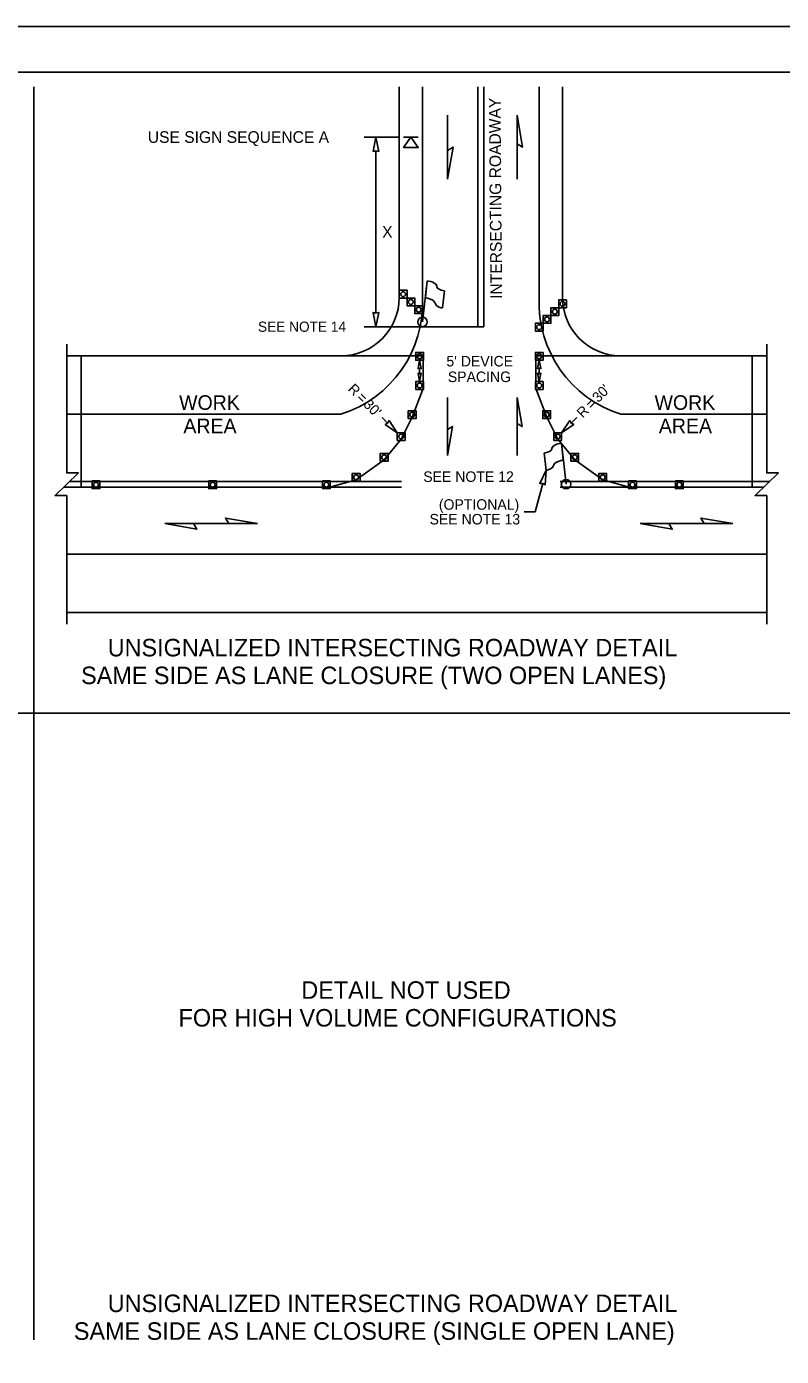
# Model space of a CAD drawing. Extents: x 99999.1 to 100095.7, y 99995 to 100010.7.
# Drawn here: x 100065.2 to 100070.38, y 100001.57 to 100010.69 of the extents above; entities that cross this region are included whole.
import ezdxf

# ---------------------------------------------------------------- set-up
doc = ezdxf.new("R2010")
doc.units = 0
for name, color, linetype in [('RD_ED_ShoulderPavedEdge', 7, 'Continuous'), ('RD_MK_LineDblYellowCenter', 7, 'Continuous'), ('RD_MK_LineEdgeWhite', 7, 'Continuous'), ('RD_MK_LineStop', 7, 'Continuous'), ('SH_DE_DetailBody1Text', 7, 'Continuous'), ('SH_DE_DetailHeading2Text', 7, 'Continuous'), ('SH_GI_PlotLimits', 7, 'Continuous'), ('SH_GI_SheetBorder', 7, 'Continuous'), ('TR_WZ_FlaggingStation', 7, 'Continuous'), ('TR_WZ_PortableSignMountBlk-Org', 7, 'Continuous'), ('TR_WZ_TrafficCone', 7, 'Continuous'), ('TR_WZ_WorkAreaLabel', 7, 'Continuous'), ('TR_WZ_WorkZoneDetails', 7, 'Continuous'), ('TR_WZ_WorkZoneTextCurrent', 7, 'Continuous')]:
    doc.layers.add(name, color=color, linetype=linetype)

msp = doc.modelspace()

# ---------------------------------------------------------------- linework, layer by layer
at = {"layer": 'RD_ED_ShoulderPavedEdge'}
for p, q in [((100065.475, 100008.4304), (100067.355, 100008.4304)), ((100069.275, 100008.4304), (100070.275, 100008.4304)), ((100065.475, 100006.6704), (100070.275, 100006.6704))]:
    msp.add_line(p, q, dxfattribs=at)
for points in [[(100067.755, 100010.275), (100067.755, 100008.8304)], [(100068.875, 100010.275), (100068.875, 100008.8304)]]:
    msp.add_lwpolyline(points, dxfattribs=at)
for centre, start, end in [((100067.355, 100008.8304), 270, 0), ((100069.275, 100008.8304), 180, 270)]:
    msp.add_arc(centre, 0.4, start, end, dxfattribs=at)
at = {"layer": 'RD_MK_LineDblYellowCenter'}
for p, q in [((100068.295, 100010.275), (100068.295, 100008.6304)), ((100068.335, 100010.275), (100068.335, 100008.6304)), ((100065.4543, 100007.5305), (100067.7712, 100007.5305)), ((100065.4957, 100007.5704), (100067.7712, 100007.5704)), ((100068.8588, 100007.5704), (100070.2957, 100007.5704)), ((100068.8588, 100007.5305), (100070.2543, 100007.5305))]:
    msp.add_line(p, q, dxfattribs=at)
at = {"layer": 'RD_MK_LineEdgeWhite'}
for p, q in [((100067.915, 100008.8304), (100067.915, 100010.275)), ((100068.715, 100008.8304), (100068.715, 100010.275)), ((100065.475, 100008.0305), (100067.355, 100008.0305)), ((100069.275, 100008.0305), (100070.275, 100008.0305)), ((100065.475, 100007.0704), (100070.275, 100007.0704))]:
    msp.add_line(p, q, dxfattribs=at)
for centre, start, end in [((100067.1158, 100008.7939), 287.39477, 2.62119), ((100069.5142, 100008.7939), 177.37881, 252.60523)]:
    msp.add_arc(centre, 0.8, start, end, dxfattribs=at)
at = {"layer": 'RD_MK_LineStop'}
msp.add_line((100067.899, 100008.6304), (100068.335, 100008.6304), dxfattribs=at)
at = {"layer": 'SH_GI_PlotLimits'}
msp.add_lwpolyline([(100059.0625, 99999.6875), (100076.0625, 99999.6875), (100076.0625, 100010.6875), (100059.0625, 100010.6875)], close=True, dxfattribs=at)
at = {"layer": 'SH_GI_SheetBorder'}
msp.add_line((100060, 100010.375), (100075.75, 100010.375), dxfattribs=at)
at = {"layer": 'TR_WZ_FlaggingStation'}
for p, q in [((100067.915, 100008.6629), (100067.9471, 100008.9439)), ((100067.934, 100008.8299), (100067.9471, 100008.9442)), ((100068.065, 100008.8764), (100068.0517, 100008.7592)), ((100067.934, 100008.8299), (100067.934, 100008.8299)), ((100068.7487, 100007.7639), (100068.762, 100007.6467)), ((100068.8797, 100007.7174), (100068.8667, 100007.8317)), ((100068.8988, 100007.5504), (100068.8667, 100007.8314)), ((100068.8797, 100007.7174), (100068.8797, 100007.7174))]:
    msp.add_line(p, q, dxfattribs=at)
for points in [[(100067.9471, 100008.9442), (100067.9528, 100008.9429), (100067.9707, 100008.9395), (100067.9845, 100008.9353), (100067.9942, 100008.9292), (100068.0027, 100008.9245), (100068.0084, 100008.9177), (100068.0126, 100008.9098), (100068.0131, 100008.9037), (100068.0185, 100008.8944), (100068.0293, 100008.887), (100068.0417, 100008.8818), (100068.065, 100008.8764)], [(100068.0517, 100008.7592), (100068.0436, 100008.7606), (100068.0259, 100008.7653), (100068.0103, 100008.7758), (100068.0037, 100008.7863), (100067.9998, 100008.7966), (100067.9907, 100008.8075), (100067.9798, 100008.8137), (100067.9624, 100008.8208), (100067.934, 100008.8299)], [(100068.8667, 100007.8317), (100068.8609, 100007.8304), (100068.8431, 100007.827), (100068.8293, 100007.8228), (100068.8196, 100007.8167), (100068.8111, 100007.812), (100068.8054, 100007.8052), (100068.8012, 100007.7973), (100068.8006, 100007.7912), (100068.7953, 100007.7819), (100068.7845, 100007.7745), (100068.7721, 100007.7693), (100068.7487, 100007.7639)], [(100068.762, 100007.6467), (100068.7702, 100007.6481), (100068.7879, 100007.6528), (100068.8035, 100007.6633), (100068.81, 100007.6738), (100068.814, 100007.6841), (100068.823, 100007.695), (100068.834, 100007.7012), (100068.8514, 100007.7083), (100068.8797, 100007.7174)]]:
    msp.add_lwpolyline(points, dxfattribs=at)
for centre in [(100067.915, 100008.6629), (100068.8988, 100007.5504)]:
    msp.add_circle(centre, 0.0325, dxfattribs=at)
at = {"layer": 'TR_WZ_PortableSignMountBlk-Org'}
msp.add_line((100067.785, 100009.9304), (100067.885, 100009.9304), dxfattribs=at)
msp.add_lwpolyline([(100067.8349, 100009.9304), (100067.885, 100009.8586), (100067.785, 100009.8586)], close=True, dxfattribs=at)
at = {"layer": 'TR_WZ_TrafficCone'}
for points in [[(100067.8083, 100008.8803), (100067.8083, 100008.827), (100067.755, 100008.827), (100067.755, 100008.8803), (100067.8083, 100008.8803)], [(100067.755, 100008.8803), (100067.755, 100008.827), (100067.8083, 100008.827), (100067.8083, 100008.8803), (100067.755, 100008.8803)], [(100067.8617, 100008.827), (100067.8617, 100008.7736), (100067.8083, 100008.7736), (100067.8083, 100008.827), (100067.8617, 100008.827)], [(100067.8083, 100008.827), (100067.8083, 100008.7736), (100067.8617, 100008.7736), (100067.8617, 100008.827), (100067.8083, 100008.827)], [(100067.915, 100008.7736), (100067.915, 100008.7203), (100067.8617, 100008.7203), (100067.8617, 100008.7736), (100067.915, 100008.7736)], [(100067.8617, 100008.7736), (100067.8617, 100008.7203), (100067.915, 100008.7203), (100067.915, 100008.7736), (100067.8617, 100008.7736)], [(100068.8483, 100008.7605), (100068.795, 100008.7605), (100068.795, 100008.7071), (100068.8483, 100008.7071), (100068.8483, 100008.7605)], [(100068.8483, 100008.7071), (100068.795, 100008.7071), (100068.795, 100008.7605), (100068.8483, 100008.7605), (100068.8483, 100008.7071)], [(100068.9016, 100008.8138), (100068.8483, 100008.8138), (100068.8483, 100008.7605), (100068.9016, 100008.7605), (100068.9016, 100008.8138)], [(100068.9016, 100008.7605), (100068.8483, 100008.7605), (100068.8483, 100008.8138), (100068.9016, 100008.8138), (100068.9016, 100008.7605)], [(100068.795, 100008.7071), (100068.7416, 100008.7071), (100068.7416, 100008.6538), (100068.795, 100008.6538), (100068.795, 100008.7071)], [(100068.795, 100008.6538), (100068.7416, 100008.6538), (100068.7416, 100008.7071), (100068.795, 100008.7071), (100068.795, 100008.6538)], [(100068.7416, 100008.6538), (100068.6883, 100008.6538), (100068.6883, 100008.6005), (100068.7416, 100008.6005), (100068.7416, 100008.6538)], [(100068.7416, 100008.6005), (100068.6883, 100008.6005), (100068.6883, 100008.6538), (100068.7416, 100008.6538), (100068.7416, 100008.6005)], [(100067.8684, 100008.4538), (100067.9217, 100008.4538), (100067.9217, 100008.4005), (100067.8684, 100008.4005), (100067.8684, 100008.4538)], [(100067.8684, 100008.4005), (100067.9217, 100008.4005), (100067.9217, 100008.4538), (100067.8684, 100008.4538), (100067.8684, 100008.4005)], [(100068.7416, 100008.4538), (100068.6883, 100008.4538), (100068.6883, 100008.4005), (100068.7416, 100008.4005), (100068.7416, 100008.4538)], [(100068.7416, 100008.4005), (100068.6883, 100008.4005), (100068.6883, 100008.4538), (100068.7416, 100008.4538), (100068.7416, 100008.4005)], [(100067.8684, 100008.2538), (100067.9217, 100008.2538), (100067.9217, 100008.2005), (100067.8684, 100008.2005), (100067.8684, 100008.2538)], [(100067.8684, 100008.2005), (100067.9217, 100008.2005), (100067.9217, 100008.2538), (100067.8684, 100008.2538), (100067.8684, 100008.2005)], [(100068.7416, 100008.2538), (100068.6883, 100008.2538), (100068.6883, 100008.2005), (100068.7416, 100008.2005), (100068.7416, 100008.2538)], [(100068.7416, 100008.2005), (100068.6883, 100008.2005), (100068.6883, 100008.2538), (100068.7416, 100008.2538), (100068.7416, 100008.2005)], [(100067.8173, 100008.0538), (100067.8707, 100008.0538), (100067.8707, 100008.0005), (100067.8173, 100008.0005), (100067.8173, 100008.0538)], [(100067.8173, 100008.0005), (100067.8707, 100008.0005), (100067.8707, 100008.0538), (100067.8173, 100008.0538), (100067.8173, 100008.0005)], [(100068.7927, 100008.0538), (100068.7393, 100008.0538), (100068.7393, 100008.0005), (100068.7927, 100008.0005), (100068.7927, 100008.0538)], [(100068.7927, 100008.0005), (100068.7393, 100008.0005), (100068.7393, 100008.0538), (100068.7927, 100008.0538), (100068.7927, 100008.0005)], [(100067.7417, 100007.9038), (100067.795, 100007.9038), (100067.795, 100007.8505), (100067.7417, 100007.8505), (100067.7417, 100007.9038)], [(100067.7417, 100007.8505), (100067.795, 100007.8505), (100067.795, 100007.9038), (100067.7417, 100007.9038), (100067.7417, 100007.8505)], [(100068.8683, 100007.9038), (100068.815, 100007.9038), (100068.815, 100007.8505), (100068.8683, 100007.8505), (100068.8683, 100007.9038)], [(100068.8683, 100007.8505), (100068.815, 100007.8505), (100068.815, 100007.9038), (100068.8683, 100007.9038), (100068.8683, 100007.8505)], [(100067.6247, 100007.7615), (100067.6781, 100007.7615), (100067.6781, 100007.7082), (100067.6247, 100007.7082), (100067.6247, 100007.7615)], [(100067.6247, 100007.7082), (100067.6781, 100007.7082), (100067.6781, 100007.7615), (100067.6247, 100007.7615), (100067.6247, 100007.7082)], [(100068.9853, 100007.7615), (100068.9319, 100007.7615), (100068.9319, 100007.7082), (100068.9853, 100007.7082), (100068.9853, 100007.7615)], [(100068.9853, 100007.7082), (100068.9319, 100007.7082), (100068.9319, 100007.7615), (100068.9853, 100007.7615), (100068.9853, 100007.7082)], [(100065.649, 100007.5738), (100065.7024, 100007.5738), (100065.7024, 100007.5205), (100065.649, 100007.5205), (100065.649, 100007.5738)], [(100065.649, 100007.5205), (100065.7024, 100007.5205), (100065.7024, 100007.5738), (100065.649, 100007.5738), (100065.649, 100007.5205)], [(100066.449, 100007.5738), (100066.5024, 100007.5738), (100066.5024, 100007.5205), (100066.449, 100007.5205), (100066.449, 100007.5738)], [(100066.449, 100007.5205), (100066.5024, 100007.5205), (100066.5024, 100007.5738), (100066.449, 100007.5738), (100066.449, 100007.5205)], [(100067.229, 100007.5738), (100067.2824, 100007.5738), (100067.2824, 100007.5205), (100067.229, 100007.5205), (100067.229, 100007.5738)], [(100067.229, 100007.5205), (100067.2824, 100007.5205), (100067.2824, 100007.5738), (100067.229, 100007.5738), (100067.229, 100007.5205)], [(100067.433, 100007.6247), (100067.4864, 100007.6247), (100067.4864, 100007.5714), (100067.433, 100007.5714), (100067.433, 100007.6247)], [(100067.433, 100007.5714), (100067.4864, 100007.5714), (100067.4864, 100007.6247), (100067.433, 100007.6247), (100067.433, 100007.5714)], [(100069.177, 100007.6247), (100069.1236, 100007.6247), (100069.1236, 100007.5714), (100069.177, 100007.5714), (100069.177, 100007.6247)], [(100069.177, 100007.5714), (100069.1236, 100007.5714), (100069.1236, 100007.6247), (100069.177, 100007.6247), (100069.177, 100007.5714)], [(100069.381, 100007.5738), (100069.3276, 100007.5738), (100069.3276, 100007.5205), (100069.381, 100007.5205), (100069.381, 100007.5738)], [(100069.381, 100007.5205), (100069.3276, 100007.5205), (100069.3276, 100007.5738), (100069.381, 100007.5738), (100069.381, 100007.5205)], [(100069.649, 100007.5738), (100069.7024, 100007.5738), (100069.7024, 100007.5205), (100069.649, 100007.5205), (100069.649, 100007.5738)], [(100069.649, 100007.5205), (100069.7024, 100007.5205), (100069.7024, 100007.5738), (100069.649, 100007.5738), (100069.649, 100007.5205)]]:
    msp.add_lwpolyline(points, dxfattribs=at)
for centre in [(100067.7817, 100008.8536), (100067.835, 100008.8003), (100067.8883, 100008.747), (100068.875, 100008.7871), (100068.7683, 100008.6805), (100068.8216, 100008.7338), (100068.715, 100008.6271), (100067.895, 100008.4271), (100068.715, 100008.4271), (100067.895, 100008.2271), (100068.715, 100008.2271), (100067.844, 100008.0271), (100068.766, 100008.0271), (100067.7683, 100007.8771), (100068.8417, 100007.8771), (100067.6514, 100007.7349), (100068.9586, 100007.7349), (100067.4597, 100007.598), (100069.1503, 100007.598), (100065.6757, 100007.5471), (100066.4757, 100007.5471), (100067.2557, 100007.5471), (100069.3543, 100007.5471), (100069.6757, 100007.5471)]:
    msp.add_circle(centre, 0.0167, dxfattribs=at)
at = {"layer": 'TR_WZ_WorkZoneDetails'}
for p, q in [((100065.25, 100010.275), (100065.25, 100001.6859)), ((100068.0855, 100009.8393), (100068.0855, 100010.0804)), ((100067.755, 100009.9304), (100067.515, 100009.9304)), ((100068.5627, 100009.8839), (100068.5627, 100009.6428)), ((100067.595, 100008.7242), (100067.595, 100009.8367)), ((100067.899, 100008.6304), (100067.515, 100008.6304)), ((100067.8951, 100008.3459), (100067.8951, 100008.3083)), ((100068.715, 100008.3459), (100068.715, 100008.3083)), ((100068.0855, 100007.9255), (100068.0855, 100008.1445)), ((100067.6754, 100007.9701), (100067.637, 100008.0085)), ((100068.5627, 100007.9659), (100068.5627, 100007.7469)), ((100068.9346, 100007.9701), (100068.973, 100008.0085)), ((100068.7385, 100007.556), (100068.688, 100007.3613)), ((100068.6118, 100007.3613), (100068.688, 100007.3613)), ((100066.3444, 100007.2805), (100066.5856, 100007.2805)), ((100066.5856, 100007.2805), (100066.3444, 100007.2805)), ((100069.6043, 100007.2805), (100069.8454, 100007.2805)), ((100069.8454, 100007.2805), (100069.6043, 100007.2805)), ((100065.25, 100005.9804), (100060, 100005.9804)), ((100070.5, 100005.9804), (100065.25, 100005.9804))]:
    msp.add_line(p, q, dxfattribs=at)
for points in [[(100068.5627, 100010.0804), (100068.6013, 100009.8616), (100068.5627, 100009.8839)], [(100067.595, 100009.9304), (100067.6143, 100009.8322), (100067.595, 100009.8367), (100067.5757, 100009.8322)], [(100068.0855, 100009.6428), (100068.124, 100009.8616), (100068.0855, 100009.8393)], [(100067.595, 100008.6304), (100067.6143, 100008.7287), (100067.595, 100008.7242), (100067.5757, 100008.7287)], [(100067.9183, 100008.4304), (100067.9183, 100008.2071), (100067.844, 100008.0105), (100067.7683, 100007.8605), (100067.7683, 100007.8605), (100067.7683, 100007.8605), (100067.6514, 100007.7182), (100067.6514, 100007.7182), (100067.6514, 100007.7182), (100067.4597, 100007.5814), (100067.279, 100007.5305), (100066.499, 100007.5305), (100065.699, 100007.5305), (100065.575, 100007.5305), (100065.575, 100008.4304)], [(100067.895, 100008.4005), (100067.9063, 100008.3433), (100067.895, 100008.3459), (100067.8838, 100008.3433)], [(100070.175, 100008.4304), (100070.175, 100007.5305), (100069.699, 100007.5305), (100069.6523, 100007.5305), (100069.6523, 100007.5305), (100069.6523, 100007.5305), (100069.331, 100007.5305), (100069.331, 100007.5305), (100069.331, 100007.5305), (100069.1503, 100007.5814), (100068.9586, 100007.7182), (100068.8417, 100007.8605), (100068.766, 100008.0105), (100068.6917, 100008.2071), (100068.6917, 100008.4304)], [(100068.7149, 100008.4005), (100068.7261, 100008.3433), (100068.7149, 100008.3459), (100068.7037, 100008.3433)], [(100067.8951, 100008.2538), (100067.9063, 100008.3109), (100067.8951, 100008.3083), (100067.8839, 100008.3109)], [(100068.715, 100008.2538), (100068.7262, 100008.3109), (100068.715, 100008.3083), (100068.7037, 100008.3109)], [(100068.5627, 100008.1445), (100068.5977, 100007.9457), (100068.5627, 100007.9659)], [(100067.7417, 100007.9038), (100067.6586, 100007.9597), (100067.6754, 100007.9701), (100067.6858, 100007.987)], [(100068.0855, 100007.7469), (100068.1205, 100007.9457), (100068.0855, 100007.9255)], [(100068.8683, 100007.9038), (100068.9514, 100007.9597), (100068.9346, 100007.9701), (100068.9242, 100007.987)], [(100068.762, 100007.6467), (100068.7187, 100007.5564), (100068.7385, 100007.556), (100068.7561, 100007.5467)], [(100066.7821, 100007.2805), (100066.5633, 100007.319), (100066.5856, 100007.2805)], [(100070.0419, 100007.2805), (100069.8231, 100007.319), (100069.8454, 100007.2805)], [(100066.1479, 100007.2805), (100066.3667, 100007.2419), (100066.3444, 100007.2805)], [(100069.4077, 100007.2805), (100069.6265, 100007.2419), (100069.6043, 100007.2805)]]:
    msp.add_lwpolyline(points, close=True, dxfattribs=at)
for points in [[(100065.475, 100006.5904), (100065.475, 100007.473), (100065.395, 100007.473), (100065.555, 100007.6279), (100065.475, 100007.6279), (100065.475, 100008.5105)], [(100070.275, 100006.5904), (100070.275, 100007.473), (100070.195, 100007.473), (100070.355, 100007.6279), (100070.275, 100007.6279), (100070.275, 100008.5105)]]:
    msp.add_lwpolyline(points, dxfattribs=at)

# ---------------------------------------------------------------- texts
at = {"layer": 'SH_DE_DetailBody1Text'}
msp.add_text('INTERSECTING ROADWAY', height=0.08, rotation=90.4626, dxfattribs=at).set_placement((100068.4607, 100008.8214))
at = {"layer": 'SH_DE_DetailHeading2Text'}
for s, p in [('UNSIGNALIZED INTERSECTING ROADWAY DETAIL', (100065.7563, 100006.3705)), ('SAME SIDE AS LANE CLOSURE (TWO OPEN LANES)', (100065.5738, 100006.1804)), ('DETAIL NOT USED', (100067.0839, 100004.0232)), ('FOR HIGH VOLUME CONFIGURATIONS', (100066.2419, 100003.8332)), ('UNSIGNALIZED INTERSECTING ROADWAY DETAIL', (100065.7563, 100001.8759)), ('SAME SIDE AS LANE CLOSURE (SINGLE OPEN LANE)', (100065.524, 100001.6859))]:
    msp.add_text(s, height=0.12, rotation=360, dxfattribs=at).set_placement(p)
at = {"layer": 'TR_WZ_WorkAreaLabel'}
for s, p in [('WORK', (100066.2458, 100008.0605)), ('WORK', (100069.5056, 100008.0605)), ('AREA', (100066.2754, 100007.9004)), ('AREA', (100069.5352, 100007.9004))]:
    msp.add_text(s, height=0.1, dxfattribs=at).set_placement(p)
at = {"layer": 'TR_WZ_WorkZoneTextCurrent'}
for s, height, p in [('USE SIGN SEQUENCE A', 0.08, (100066.0313, 100009.8904)), ('X', 0.08, (100067.6379, 100009.2404)), ('SEE NOTE 14', 0.07, (100066.7868, 100008.5954)), ("5' DEVICE", 0.072, (100068.0784, 100008.3579)), ('SPACING', 0.072, (100068.0883, 100008.2509)), ('SEE NOTE 12', 0.072, (100067.9199, 100007.5665)), ('(OPTIONAL)', 0.072, (100068.0267, 100007.3757)), ('SEE NOTE 13', 0.072, (100067.9632, 100007.2749))]:
    msp.add_text(s, height=height, dxfattribs=at).set_placement(p)
for s, rotation, p in [('R', 315, (100067.3982, 100008.1977)), ("30'", 45, (100069.1202, 100008.1062)), ('=', 315, (100067.4574, 100008.1386)), ("30'", 315, (100067.5042, 100008.0917)), ('=', 45, (100069.0734, 100008.0593)), ('R', 45, (100069.0142, 100008.0002))]:
    msp.add_text(s, height=0.07, rotation=rotation, dxfattribs=at).set_placement(p)

doc.saveas('drawing.dxf')
